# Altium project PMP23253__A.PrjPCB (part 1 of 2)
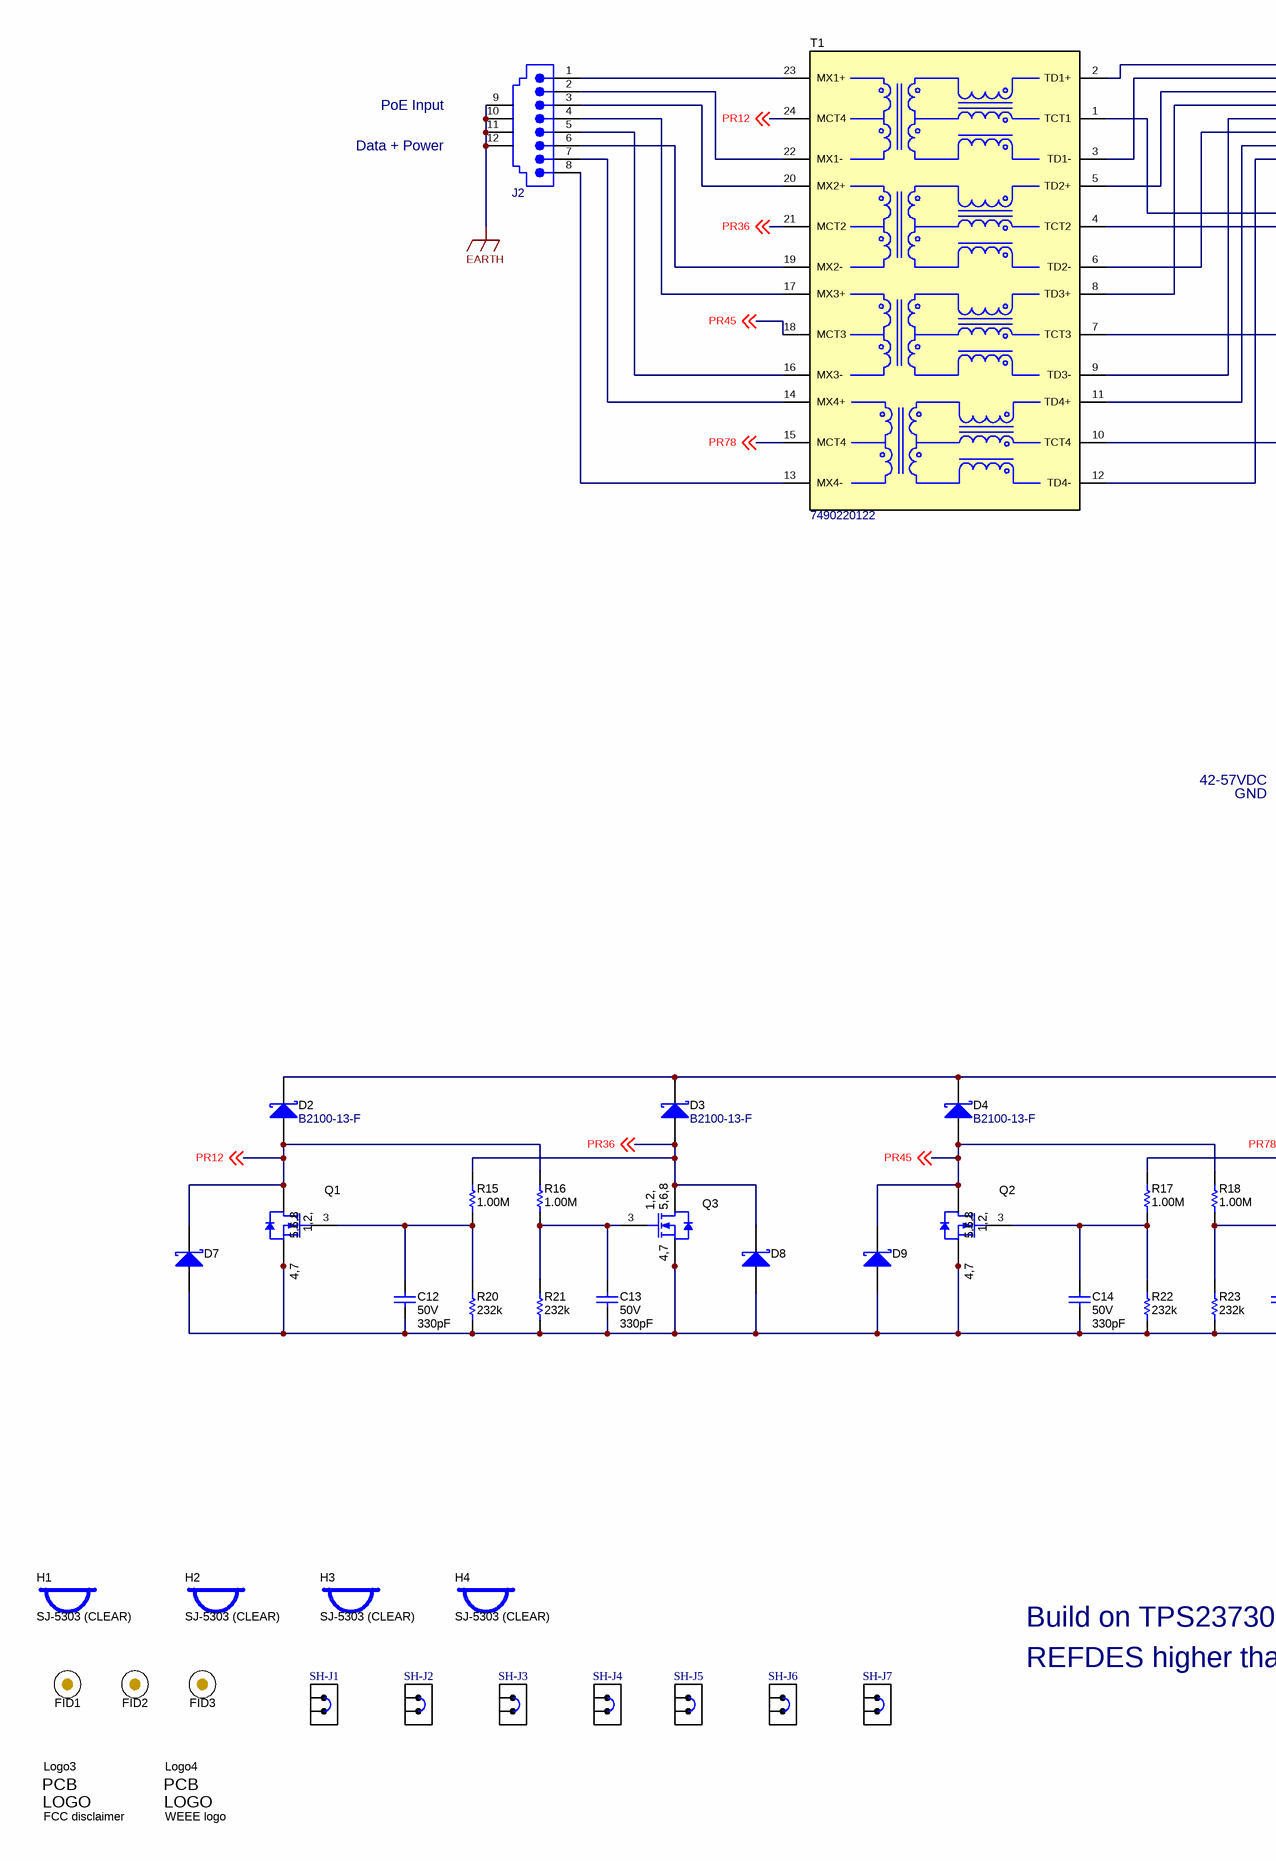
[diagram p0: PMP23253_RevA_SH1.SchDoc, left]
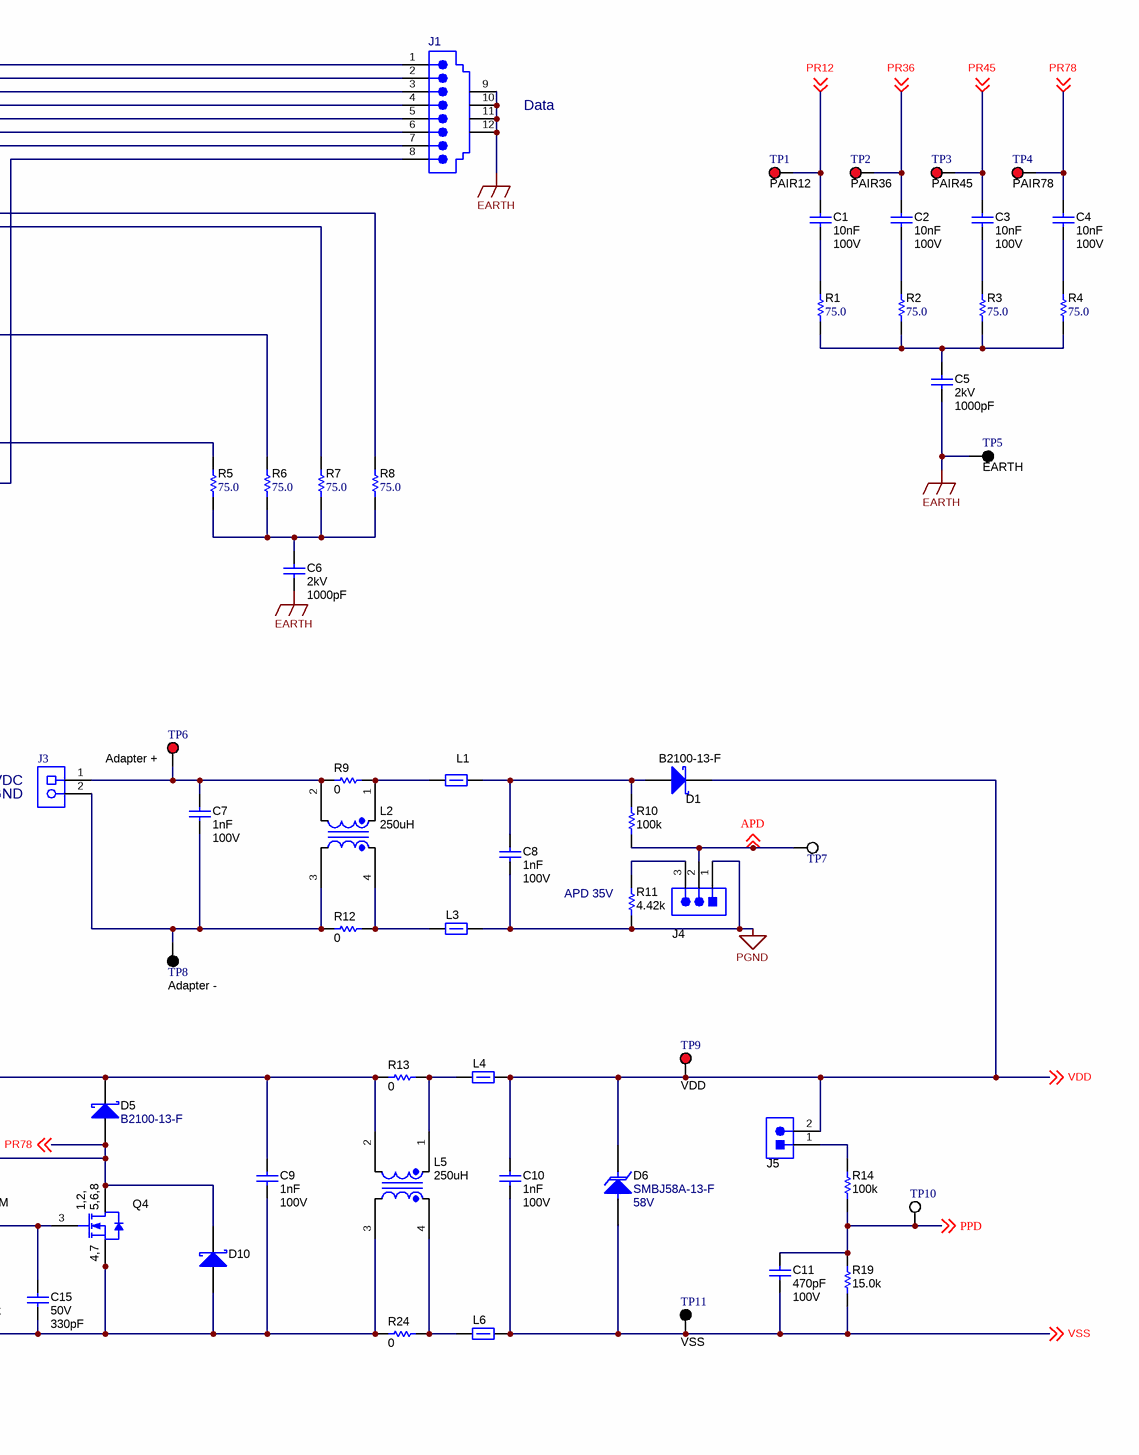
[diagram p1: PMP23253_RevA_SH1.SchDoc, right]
CopyrightYear: 2022; PCB_Layout: N/A; PCB_Rev: A; PRJ_Customer: Public Release; PRJ_Engineer: D Strasser; PRJ_Number: PMP23253; PRJ_Title: Active Clamp Forward Converter, 15V/3.3A; SCH_Rev: A; TechSupport: N/A; TID: N/A
2 sheets, 242 parts. Net scope: global (net labels, ports and power ports of the same name join across sheets).
Board file: PMP23253_ReA.PcbDoc
Sheets:
  PMP23253_RevA_SH1.SchDoc
  PMP23253_RevA_SH2.SchDoc

## Sheet PMP23253_RevA_SH1.SchDoc: PoE Input
size 558 x 431 mm; Date: Not shown in title block; ApprovedBy: Not shown in title block; CheckedBy: Not shown in title block; Author: Not shown in title block; CompanyName: Not shown in title block; DrawnBy: D Strasser; Engineer: Not shown in title block; Organization: Not shown in title block; Address1: Not shown in title block; Address2: Not shown in title block; Address3: Not shown in title block; Address4: Not shown in title block; DocumentNumber: 1; Revision: Use project parameter SCH_Rev; SheetNumber: 1; SheetTotal: 2; PageSetup: Record=PageOptions¦CenterHorizontal=True¦CenterVertical=True¦PrintScale=1.00¦XCorrection=1.00¦YCorrection=1.00¦PrintKind=0¦BorderSize=5000000¦LeftOffset=0¦BottomOffset=0¦Orientation=2¦PaperLength=1000¦PaperWidth=1000¦Scale=100¦PaperSource=15¦PrintQuality=600¦MediaType=1¦DitherType=10¦PaperKind=Letter¦PrintScaleMode=1

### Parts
C1  Cap_F: 10nF  VDC_V: 100V  [0603]  (hidden comment: CGA3E2X7R2A103K080AA)
C2  Cap_F: 10nF  VDC_V: 100V  [0603]  (hidden comment: CGA3E2X7R2A103K080AA)
C3  Cap_F: 10nF  VDC_V: 100V  [0603]  (hidden comment: CGA3E2X7R2A103K080AA)
C4  Cap_F: 10nF  VDC_V: 100V  [0603]  (hidden comment: CGA3E2X7R2A103K080AA)
C5  VDC_V: 2kV  ValueDisplayed: 1000pF  [1808]  (hidden comment: GR442QR73D102KW01L)
C6  VDC_V: 2kV  ValueDisplayed: 1000pF  [1808]  (hidden comment: GR442QR73D102KW01L)
C7  Cap_F: 1nF  VDC_V: 100V  [0603]  (hidden comment: C1608X7R2A102K080AA)
C8  Cap_F: 1nF  VDC_V: 100V  [0603]  (hidden comment: C1608X7R2A102K080AA)
C9  Cap_F: 1nF  VDC_V: 100V  [0603]  (hidden comment: C1608X7R2A102K080AA)
C10  Cap_F: 1nF  VDC_V: 100V  [0603]  (hidden comment: C1608X7R2A102K080AA)
C11  Cap_F: 470pF  VDC_V: 100V  [0805_HV]  (hidden comment: 08051C471KAT2A)
C12  VDC_V: 50V  ValueDisplayed: 330pF  [0603]  (hidden comment: 885012006060)
C13  VDC_V: 50V  ValueDisplayed: 330pF  [0603]  (hidden comment: 885012006060)
C14  VDC_V: 50V  ValueDisplayed: 330pF  [0603]  (hidden comment: 885012006060)
C15  VDC_V: 50V  ValueDisplayed: 330pF  [0603]  (hidden comment: 885012006060)
D1  PartNumber: B2100-13-F  [SMB]  (hidden comment: CMP-0028397-2)
D2  B2100-13-F  [SMB]
D3  B2100-13-F  [SMB]
D4  B2100-13-F  [SMB]
D5  B2100-13-F  [SMB]
D6  SMBJ58A-13-F  value 58V  [SMB]
D7  CMP-0028397-2  [SMB]  (value not drawn)
D8  CMP-0028397-2  [SMB]  (value not drawn)
D9  CMP-0028397-2  [SMB]  (value not drawn)
D10  CMP-0028397-2  [SMB]  (value not drawn)
FID1  Fiducial  [Fiducial10-20]  (value not drawn)
FID2  Fiducial  [Fiducial10-20]  (value not drawn)
FID3  Fiducial  [Fiducial10-20]  (value not drawn)
H1  SJ-5303 (CLEAR)  [Bumpon_SJ5003Transparent]
H2  SJ-5303 (CLEAR)  [Bumpon_SJ5003Transparent]
H3  SJ-5303 (CLEAR)  [Bumpon_SJ5003Transparent]
H4  SJ-5303 (CLEAR)  [Bumpon_SJ5003Transparent]
J1  1-406541-1  [TEC_1-406541-1]  (value not drawn)
J2  1-406541-1  [TEC_1-406541-1]  (value not drawn)
J3  ED555/2DS  [TERM_BLK_ED555-2DS]  (value not drawn)
J4  5-146278-3  [TE_5-146278-3]  (value not drawn)
J5  5-146278-2  [TE_5-146278-2]  (value not drawn)
L1  742792641  [0603]  (value not drawn)
L2  value 250uH  [WE-SL5]  (hidden comment: 744272251)
L3  742792641  [0603]  (value not drawn)
L4  742792641  [0603]  (value not drawn)
L5  value 250uH  [WE-SL5]  (hidden comment: 744272251)
L6  742792641  [0603]  (value not drawn)
Logo3  FCC disclaimer  [FCC_disclaimer]  (no BOM)
Logo4  WEEE logo  [WEEE_Minimum]  (no BOM)
Q1  CSD19538Q2  [DQK0006C]  (value not drawn)
Q2  CSD19538Q2  [DQK0006C]  (value not drawn)
Q3  CSD19538Q2  [DQK0006C]  (value not drawn)
Q4  CSD19538Q2  [DQK0006C]  (value not drawn)
R1  ValueDisplayed: 75.0  [0603]  (hidden comment: RC0603FR-0775RL)
R2  ValueDisplayed: 75.0  [0603]  (hidden comment: RC0603FR-0775RL)
R3  ValueDisplayed: 75.0  [0603]  (hidden comment: RC0603FR-0775RL)
R4  ValueDisplayed: 75.0  [0603]  (hidden comment: RC0603FR-0775RL)
R5  ValueDisplayed: 75.0  [0603]  (hidden comment: RC0603FR-0775RL)
R6  ValueDisplayed: 75.0  [0603]  (hidden comment: RC0603FR-0775RL)
R7  ValueDisplayed: 75.0  [0603]  (hidden comment: RC0603FR-0775RL)
R8  ValueDisplayed: 75.0  [0603]  (hidden comment: RC0603FR-0775RL)
R9  ValueDisplayed: 0  [0805_HV]  (hidden comment: PMR10EZPJ000)
R10  ValueDisplayed: 100k  [0603]  (hidden comment: CRCW0603100KFKEA)
R11  ValueDisplayed: 4.42k  [0603]  (hidden comment: CRCW06034K42FKEA)
R12  ValueDisplayed: 0  [0805_HV]  (hidden comment: PMR10EZPJ000)
R13  ValueDisplayed: 0  [0805_HV]  (hidden comment: PMR10EZPJ000)
R14  ValueDisplayed: 100k  [0603]  (hidden comment: CRCW0603100KFKEA)
R15  ValueDisplayed: 1.00M  [0603]  (hidden comment: CRCW06031M00FKEA)
R16  ValueDisplayed: 1.00M  [0603]  (hidden comment: CRCW06031M00FKEA)
R17  ValueDisplayed: 1.00M  [0603]  (hidden comment: CRCW06031M00FKEA)
R18  ValueDisplayed: 1.00M  [0603]  (hidden comment: CRCW06031M00FKEA)
R19  ValueDisplayed: 15.0k  [0603]  (hidden comment: CRCW060315K0FKEA)
R20  ValueDisplayed: 232k  [0603]  (hidden comment: CRCW0603232KFKEA)
R21  ValueDisplayed: 232k  [0603]  (hidden comment: CRCW0603232KFKEA)
R22  ValueDisplayed: 232k  [0603]  (hidden comment: CRCW0603232KFKEA)
R23  ValueDisplayed: 232k  [0603]  (hidden comment: CRCW0603232KFKEA)
R24  ValueDisplayed: 0  [0805_HV]  (hidden comment: PMR10EZPJ000)
SH-J1  60900213421  [Wurth_60900213421]  (value not drawn)
SH-J2  60900213421  [Wurth_60900213421]  (value not drawn)
SH-J3  60900213421  [Wurth_60900213421]  (value not drawn)
SH-J4  60900213421  [Wurth_60900213421]  (value not drawn)
SH-J5  60900213421  [Wurth_60900213421]  (value not drawn)
SH-J6  60900213421  [Wurth_60900213421]  (value not drawn)
SH-J7  60900213421  [Wurth_60900213421]  (value not drawn)
T1  7490220122  [Wurth_7490220122]
TP1  PAIR12  [Keystone5000]
TP2  PAIR36  [Keystone5000]
TP3  PAIR45  [Keystone5000]
TP4  PAIR78  [Keystone5000]
TP5  EARTH  [Keystone5001]
TP6  Adapter +  [Keystone5000]
TP7  5002  [Keystone5002]  (value not drawn)
TP8  Adapter -  [Keystone5001]
TP9  VDD  [Keystone5000]
TP10  5002  [Keystone5002]  (value not drawn)
TP11  VSS  [Keystone5001]

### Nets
EARTH: C5.1 C6.1 J1.9 J1.10 J1.11 J1.12 J2.9 J2.10 J2.11 J2.12 TP5.1
PGND: C8.2 J4.1 L3.2 R11.1
APD: J4.2 R10.1 TP7.1 ; off-sheet APD
PPD: C11.1 R14.2 R19.2 TP10.1 ; off-sheet PPD
PR12: C1.2 D2.2(A) D7.1(K) Q1.1(D) Q1.2(D) Q1.5(D) Q1.6(D) Q1.8(D) R16.2 T1.24(MCT4) TP1.1 ; off-sheet PR12
PR36: C2.2 D3.2(A) D8.1(K) Q3.1(D) Q3.2(D) Q3.5(D) Q3.6(D) Q3.8(D) R15.2 T1.21(MCT2) TP2.1 ; off-sheet PR36
PR45: C3.2 D4.2(A) D9.1(K) Q2.1(D) Q2.2(D) Q2.5(D) Q2.6(D) Q2.8(D) R18.2 T1.18(MCT3) TP3.1 ; off-sheet PR45
PR78: C4.2 D5.2(A) D10.1(K) Q4.1(D) Q4.2(D) Q4.5(D) Q4.6(D) Q4.8(D) R17.2 T1.15(MCT4) TP4.1 ; off-sheet PR78
VDD: C10.1 D1.1(K) D6.1(K) J5.2 L4.2 TP9.1 ; off-sheet VDD
VSS: C10.2 C11.2 D6.2(A) L6.2 R19.1 TP11.1 ; off-sheet VSS
NetC1_1: C1.1 R1.1
NetC2_1: C2.1 R2.1
NetC3_1: C3.1 R3.1
NetC4_1: C4.1 R4.1
NetC5_2: C5.2 R1.2 R2.2 R3.2 R4.2
NetC6_2: C6.2 R5.2 R6.2 R7.2 R8.2
NetC7_1: C7.1 J3.1 L2.2 R9.1 TP6.1
NetC7_2: C7.2 J3.2 L2.3 R12.1 TP8.1
NetC8_1: C8.1 D1.2(A) L1.2 R10.2
NetC9_1: C9.1 D2.1(K) D3.1(K) D4.1(K) D5.1(K) L5.2 R13.1
NetC9_2: C9.2 C12.2 C13.2 C14.2 C15.2 D7.2(A) D8.2(A) D9.2(A) D10.2(A) L5.3 Q1.4(S) Q1.7(S) Q2.4(S) Q2.7(S) Q3.4(S) Q3.7(S) Q4.4(S) Q4.7(S) R20.1 R21.1 R22.1 R23.1 R24.1
NetC12_1: C12.1 Q1.3(G) R15.1 R20.2
NetC13_1: C13.1 Q3.3(G) R16.1 R21.2
NetC14_1: C14.1 Q2.3(G) R17.1 R22.2
NetC15_1: C15.1 Q4.3(G) R18.1 R23.2
NetJ1_1: J1.1 T1.2(TD1+)
NetJ1_2: J1.2 T1.3(TD1-)
NetJ1_3: J1.3 T1.5(TD2+)
NetJ1_4: J1.4 T1.8(TD3+)
NetJ1_5: J1.5 T1.9(TD3-)
NetJ1_6: J1.6 T1.6(TD2-)
NetJ1_7: J1.7 T1.11(TD4+)
NetJ1_8: J1.8 T1.12(TD4-)
NetJ2_1: J2.1 T1.23(MX1+)
NetJ2_2: J2.2 T1.22(MX1-)
NetJ2_3: J2.3 T1.20(MX2+)
NetJ2_4: J2.4 T1.17(MX3+)
NetJ2_5: J2.5 T1.16(MX3-)
NetJ2_6: J2.6 T1.19(MX2-)
NetJ2_7: J2.7 T1.14(MX4+)
NetJ2_8: J2.8 T1.13(MX4-)
NetJ4_3: J4.3 R11.2
NetJ5_1: J5.1 R14.1
NetL1_1: L1.1 L2.1 R9.2
NetL2_4: L2.4 L3.1 R12.2
NetL4_1: L4.1 L5.1 R13.2
NetL5_4: L5.4 L6.1 R24.2
NetR5_1: R5.1 T1.10(TCT4)
NetR6_1: R6.1 T1.7(TCT3)
NetR7_1: R7.1 T1.4(TCT2)
NetR8_1: R8.1 T1.1(TCT1)

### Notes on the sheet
- PoE Input
- Data + Power
- Data
- (near J3) 42-57VDC
- (near J3) GND
- (near R11) APD 35V
- Build on TPS23730EVM-093
- REFDES higher than 99 not on PCB

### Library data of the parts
C1-C4 = CMP-0007082-4: CAP, CERM, 0.01 uF, 100 V, +/- 10%, X7R, AEC-Q200 Grade 1, 0603; Manufacturer: TDK; TaMin_C: -55°C; ESR_ohm: 0.235428; Polarized: N; SizeAreaWB_mm2: 4.68; Value1: 0.235428 ohm; U/M: EA; Value: 0.01uF; TaMax_C: 125°C; SizeZ_mm: 1; SizeX_mm: 1.6; SizeY_mm: 0.8; SizeArea_mm2: 1.28; AEC Qualified: Y; IRMS_A: 396.995mA; AEC Category: Q200
C5 C6 = CMP-0009436-2: CAP, CERM, 1000 pF, 2000 V, +/- 10%, X7R, 1808; Manufacturer: MuRata; TaMin_C: -55°C; Polarized: N; SizeAreaWB_mm2: 16.5; Value1: Unknown; U/M: EA; Value: 1000pF; TaMax_C: 125°C; SizeZ_mm: 2.03; SizeX_mm: 4.5; SizeY_mm: 2; Value2: 2000V; SizeArea_mm2: 9; Cap_F: 1nF; AEC Category: Q200
C7-C10 = CMP-0007053-4: CAP, CERM, 1000 pF, 100 V, +/- 10%, X7R, 0603; Manufacturer: TDK; TaMin_C: -55°C; Polarized: N; SizeAreaWB_mm2: 4.68; Value1: Unknown; U/M: EA; Value: 1000pF; TaMax_C: 125°C; SizeZ_mm: 1; SizeX_mm: 1.6; SizeY_mm: 0.8; SizeArea_mm2: 1.28; AEC Category: Q200
C11 = CMP-0007557-2: CAP, CERM, 470 pF, 100 V, +/- 10%, X7R, 0805; Manufacturer: AVX; TaMin_C: -55°C; ESR_ohm: 0.454; Polarized: N; SizeAreaWB_mm2: 6.75; Value1: 0.454 ohm; U/M: EA; Value: 470pF; TaMax_C: 125°C; SizeZ_mm: 1.45; SizeX_mm: 2; SizeY_mm: 1.25; Cap_Case: 0805; SizeArea_mm2: 2.5; AEC Category: Q200
C12-C15 = CMP-0006823-4: CAP, CERM, 330 pF, 50 V, +/- 5%, C0G/NP0, 0603; Manufacturer: Wurth Elektronik; TaMin_C: -55°C; Polarized: N; SizeAreaWB_mm2: 4.68; Value1: Unknown; U/M: EA; Value: 330pF; TaMax_C: 125°C; SizeZ_mm: 1; SizeX_mm: 1.6; SizeY_mm: 0.8; SizeArea_mm2: 1.28; AEC Category: Q200
D1 = CMP-0028397-2: Diode, Schottky, 100 V, 2 A, SMB; Manufacturer: Diodes Inc.; Vf_V: 790mV; Value: 100V; Value1: 2A; Value2: 0.79V; TJmax_C: 150°C; RJC_CperW: 15; SizeArea_mm2: 21.336; Green_REACh: Passed; Green_Lifecycle: Active; SizeY_mm: 3.81; AEC Category: Q101; SizeZ_mm: 2.6; SizeAreaWB_mm2: 44.156; SizeX_mm: 5.6
D2-D5 = CMP-0028397-2: Diode, Schottky, 100 V, 2 A, SMB; Manufacturer: Diodes Inc.; Value2: 0.79V; Value1: 2A; SizeArea_mm2: 21.336; Value: 100V; Green_REACh: Passed; Green_Lifecycle: Active; Vf_V: 790mV; SizeY_mm: 3.81; AEC Category: Q101; SizeZ_mm: 2.6; TJmax_C: 150°C; RJC_CperW: 15; SizeAreaWB_mm2: 44.156; SizeX_mm: 5.6
D6 = CMP-0005583-3: Diode, TVS, Uni, 58 V, 93.6 Vc, SMB; Manufacturer: Diodes Inc.; Vbr_Max: 74.6V; AEC Category: Q101; Ppk: 600W; Vbr_Min: 64.4V; SizeX_mm: 5.6; SizeZ_mm: 2.6; SizeY_mm: 3.81; Ipp: 6.4A; Vc: 93.6V; SizeAreaWB_mm2: 44.156; SizeArea_mm2: 21.336
D7-D10 = CMP-0028397-2: Diode, Schottky, 100 V, 2 A, SMB; PartNumber: B2100-13-F; Manufacturer: Diodes Inc.; Vf_V: 790mV; Value: 100V; Value1: 2A; Value2: 0.79V; TJmax_C: 150°C; RJC_CperW: 15; SizeArea_mm2: 21.336; Green_REACh: Passed; Green_Lifecycle: Active; SizeY_mm: 3.81; AEC Category: Q101; SizeZ_mm: 2.6; SizeAreaWB_mm2: 44.156; SizeX_mm: 5.6
FID1-FID3 = CMP-0077181-1: Fiducial mark.  There is nothing to buy or mount.
H1-H4 = CMP-0003620-1: Bumpon, Hemisphere, 0.44 X 0.20, Clear; Manufacturer: 3M
J1 J2 = CMP-0054918-1: RJ45, No LED, tab up, R/A, TH; Manufacturer: TE Connectivity; CNHeader: FALSE; Green_Lifecycle: Active; Green_REACh: Passed; ContactFinish: Gold; CT: TRUE
J3 = CMP-0074913-1: Terminal Block, 3.5mm Pitch, 2x1, TH; Manufacturer: On-Shore Technology; Cert_VDE: Y; CNHeader: False; Current_A: 6A; Green_Lifecycle: Active; Shrouded: N; Gender: Female; Green_REACh: Passed; Voltage_V: 150V; Row_Count: 1; Pitch_mm: 3.5; ContactFinish: Brass; CT: True
J4 = CMP-0054951-1: Header, 100mil, 3x1, Tin, TH; Manufacturer: TE Connectivity; CNHeader: TRUE; Green_Lifecycle: Active; Green_REACh: Passed; CT: FALSE
J5 = CMP-0054952-1: Header, 100mil, 2x1, Tin, TH; Manufacturer: TE Connectivity; CNHeader: TRUE; Green_Lifecycle: Active; Green_REACh: Passed; CT: FALSE
L1 L3 L4 L6 = CMP-0003192-2: Ferrite Bead, 300 ohm @ 100 MHz, 2 A, 0603; Manufacturer: Wurth Elektronik; Ztyp@1GHz_Ohm: 273.989; ZTyp@100MHz_Ohm: 300; SizeAreaWB_mm2: 4.68; DCR_ohm: 0.15; Value1: 0.15 ohm; Value: 300 ohm; Imax_A: 2A; SizeZ_mm: 1; SizeX_mm: 1.6; SizeY_mm: 0.8; SizeArea_mm2: 1.28
L2 L5 = CMP-0013220-2: Coupled inductor, 250 uH,  A, 0.035 ohm, SMD; Manufacturer: Wurth Elektronik; DCR_ohm: 0.035; Ind_H: 250µH
Logo3 = CMP-0074847-1: FCC_disclaimer; Library Reference: Logo
Logo4 = CMP-0074769-1
Q1-Q4 = CMP-0000968-2: MOSFET, N-CH, 100 V, 4.5 A, DQK0006C (WSON-6); Alternate Manufacturer: None; Manufacturer: Texas Instruments; SizeZ_mm: 0.8; ChType: N; VdsMax_V: 100V; SizeX_mm: 2; SizeAreaWB_mm2: 9; Vgs_V: 20V; Value: 100V; SizeArea_mm2: 4; AEC Category: Q101; IdsMax_A: 4.5A; U/M: EA
R1-R8 = CMP-0023268-5: RES, 75.0, 1%, 0.1 W, 0603; Manufacturer: Yageo; Power_W: 100mW; TempCo: 100 ppm/C; Value_Code: 75R0; Value: 75.0; EIA_Code: E96; Res_ohm: 75; SizeX_mm: 1.6; SizeY_mm: 0.8; SizeZ_mm: 1; Value2: 0.1W; SizeArea_mm2: 1.28; AEC Qualified: N; VDC_V: 75V; AEC Category: Q200; SizeAreaWB_mm2: 4.68
R9 R12 R13 R24 = CMP-0081857-1: RES, 0, 0%,  W, AEC-Q200 Grade 0, 0805; Manufacturer: Rohm; SizeAreaWB_mm2: 6.75; SizeArea_mm2: 2.5; AEC Qualified: Y; AEC Category: Q200; Value: 0; SizeZ_mm: 1.45; SizeY_mm: 1.25; SizeX_mm: 2
R10 R14 = CMP-0021990-4: RES, 100 k, 1%, 0.1 W, AEC-Q200 Grade 0, 0603; Manufacturer: Vishay-Dale; Power_W: 100mW; TempCo: 100 ppm/C; Value: 100k; EIA_Code: E96; SizeX_mm: 1.6; SizeY_mm: 0.8; SizeZ_mm: 1; Value2: 0.1W; SizeArea_mm2: 1.28; AEC Qualified: Y; VDC_V: 75V; AEC Category: Q200; AEC Grade: 0
R11 = CMP-0022453-4: RES, 4.42 k, 1%, 0.1 W, AEC-Q200 Grade 0, 0603; Manufacturer: Vishay-Dale; Power_W: 100mW; TempCo: 100 ppm/C; Value_Code: 4k42; Value: 4.42k; EIA_Code: E96; SizeX_mm: 1.6; SizeY_mm: 0.8; SizeZ_mm: 1; Value2: 0.1W; SizeArea_mm2: 1.28; AEC Qualified: Y; VDC_V: 75V; AEC Category: Q200; AEC Grade: 0
R15-R18 = CMP-0022138-4: RES, 1.00 M, 1%, 0.1 W, AEC-Q200 Grade 0, 0603; Manufacturer: Vishay-Dale; Power_W: 100mW; TempCo: 100 ppm/C; Value_Code: 1M00; Value: 1.00Meg; EIA_Code: E96; Res_ohm: 1M; SizeX_mm: 1.6; SizeY_mm: 0.8; SizeZ_mm: 1; Value2: 0.1W; SizeArea_mm2: 1.28; AEC Qualified: Y; VDC_V: 75V; AEC Category: Q200; AEC Grade: 0
R19 = CMP-0022066-4: RES, 15.0 k, 1%, 0.1 W, AEC-Q200 Grade 0, 0603; Manufacturer: Vishay-Dale; Power_W: 100mW; TempCo: 100 ppm/C; Value_Code: 15k0; Value: 15.0k; EIA_Code: E96; Res_ohm: 15k; SizeX_mm: 1.6; SizeY_mm: 0.8; SizeZ_mm: 1; Value2: 0.1W; SizeArea_mm2: 1.28; AEC Qualified: Y; VDC_V: 75V; AEC Category: Q200; AEC Grade: 0
R20-R23 = CMP-0022224-4: RES, 232 k, 1%, 0.1 W, AEC-Q200 Grade 0, 0603; Manufacturer: Vishay-Dale; Power_W: 100mW; TempCo: 100 ppm/C; Value: 232k; EIA_Code: E96; SizeX_mm: 1.6; SizeY_mm: 0.8; SizeZ_mm: 1; Value2: 0.1W; SizeArea_mm2: 1.28; AEC Qualified: Y; VDC_V: 75V; AEC Category: Q200; AEC Grade: 0
SH-J1-SH-J7 = CMP-0003761-2: Shunt, 2.54mm, Gold, Black; Manufacturer: Wurth Elektronik
T1 = CMP-0030597-1: Transformer, 350 uH, SMT; Manufacturer: Wurth Elektronik; Value: 350uH; Ind_H: 350µH; Lp: 350
TP1-TP4 TP6 TP9 = CMP-0055137-2: Test Point, Miniature, Red, TH; Manufacturer: Keystone Electronics; Green_REACh: Passed; Green_Lifecycle: Active; ContactFinish: Silver; CNHeader: FALSE; CT: TRUE
TP5 TP8 TP11 = CMP-0055138-2: Test Point, Miniature, Black, TH; Manufacturer: Keystone Electronics; ContactFinish: Silver; CNHeader: FALSE; Green_Lifecycle: Active; Green_REACh: Passed; CT: TRUE
TP7 TP10 = CMP-0055139-2: Test Point, Miniature, White, TH; Manufacturer: Keystone Electronics; ContactFinish: Silver; Green_REACh: Passed; CT: TRUE; Green_Lifecycle: Active; CNHeader: FALSE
